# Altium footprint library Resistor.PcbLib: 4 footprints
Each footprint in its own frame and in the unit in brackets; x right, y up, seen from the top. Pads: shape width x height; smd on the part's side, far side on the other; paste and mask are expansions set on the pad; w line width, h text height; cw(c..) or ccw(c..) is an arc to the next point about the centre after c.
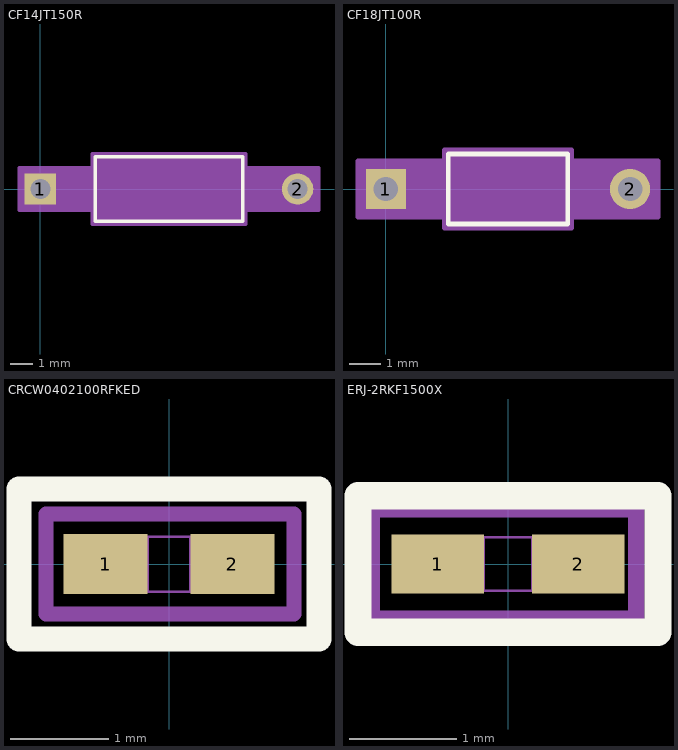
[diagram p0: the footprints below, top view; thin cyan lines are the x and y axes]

## CF14JT150R [mil] "150 Ohms ±5% 0.25W, 1/4W Through Hole Resistor Axial Carbon Film"
pads (2):
  rect 55x55 / inner round 60 / far side rect 55x55 hole 35 paste-99999 mask+0: 1(0,0)
  round 55 / inner round 60 / far side round 55 hole 35 paste-99999 mask+0: 2(450,0)
Top Overlay:
  lines w6: 96,-56.5 96,56.5 354,56.5 354,-56.5 96,-56.5
Mechanical 13:
  lines w1: 0,0 101,0 ; 349,0 450,0 ; 101,-51.5 101,51.5 349,51.5 349,-51.5 101,-51.5
  text "RefDes2" at 137.5,-25 h50
Mechanical 15:
  region: 91,-37.5 -37.5,-37.5 -37.5,37.5 91,37.5 91,61.5 359,61.5 359,37.5 487.5,37.5 487.5,-37.5 359,-37.5 359,-61.5 91,-61.5
  lines w6: -37.5,-37.5 91,-37.5 91,-61.5 359,-61.5 359,-37.5 487.5,-37.5 487.5,37.5 359,37.5 359,61.5 91,61.5 91,37.5 -37.5,37.5 -37.5,-37.5
3D body "STA_CF14_STP.step": height 103, standoff -110, extent -12.48,-52.25 462.48,50

## CF18JT100R [mil] "100 Ohms ±5% 0.125W, 1/8W Through Hole Resistor Axial Carbon Film"
pads (2):
  rect 51x51 hole 31 paste-99999 mask+0: 1(0,0)
  round 51 hole 31 paste-99999 mask+0: 2(310,0)
Top Overlay:
  lines w6: 79,-44.5 231,-44.5 231,44.5 79,44.5 79,-44.5
Mechanical 13:
  lines w1: 0,0 84,0 ; 226,0 310,0 ; 84,-39.5 226,-39.5 226,39.5 84,39.5 84,-39.5
Mechanical 15:
  region: 74,-35.5 -35.5,-35.5 -35.5,35.5 74,35.5 74,49.5 236,49.5 236,35.5 345.5,35.5 345.5,-35.5 236,-35.5 236,-49.5 74,-49.5
  lines w6: -35.5,-35.5 -35.5,35.5 74,35.5 74,49.5 236,49.5 236,35.5 345.5,35.5 345.5,-35.5 236,-35.5 236,-49.5 74,-49.5 74,-35.5 -35.5,-35.5
3D body "STA_CF18_STP.step": height 78.99, standoff -110, extent -10.51,-39.21 320.51,39.21

## CRCW0402100RFKED [mil] "100 Ohms ±1% 0.063W, 1/16W Chip Resistor 0402 (1005 Metric) Automotive AEC-Q200 Thick Film"
pads (2):
  rect 33.65x23.97 smd paste+0 mask+0: 1(-25.33,0) 2(25.33,0)
Top Overlay:
  lines w10: -60,-30 60,-30 60,30 -60,30 -60,-30
Mechanical 13:
  lines w1: -20.5,-11 -20.5,11 ; -20.5,-11 20.5,-11 ; -20.5,-11 -8.5,-11 -8.5,11 -20.5,11 ; -20.5,-11 -20.5,11 ; -20.5,11 20.5,11 ; 20.5,-11 20.5,11 ; 20.5,-11 20.5,11 ; 20.5,-11 8.5,-11 8.5,11 20.5,11
Mechanical 15:
  lines w6: -49.16,-20 -49.16,-5.99 -49.16,20 -19.09,20 19.09,20 50,20 50,10 50,-10 50,-20 -49.16,-20
3D body "RES_CRCW_0402.step": height 15.98, standoff 0, extent -20.51,-10.98 20.51,10.98

## ERJ-2RKF1500X [mil] "150 Ohms ±1% 0.1W, 1/10W Chip Resistor 0402 (1005 Metric) Automotive AEC-Q200 Thick Film"
pads (2):
  rect 33.81x21.68 smd paste+0 mask+0: 1(-25.76,0) 2(25.76,0)
Top Overlay:
  lines w10: -55,-25 55,-25 55,25 -55,25 -55,-25
Mechanical 13:
  lines w1: -20.67,-9.84 -20.67,9.84 ; -20.67,-9.84 20.67,-9.84 ; -20.67,-9.84 -8.86,-9.84 -8.86,9.84 -20.67,9.84 ; -20.67,-9.84 -20.67,9.84 ; -20.67,9.84 20.67,9.84 ; 20.67,-9.84 20.67,9.84 ; 20.67,-9.84 20.67,9.84 ; 20.67,-9.84 8.86,-9.84 8.86,9.84 20.67,9.84
Mechanical 15:
  lines w6: -48.49,-20 -46.87,-20 -31.33,-20 31.33,-20 45,-20 ; -39.1,-20 -50,-20 -50,-15.42 -50,20 -31.33,20 31.33,20 47,20 47,-20
3D body "RC0402N_PAN.step": height 27.99, standoff 0, extent -20.67,-9.84 20.67,9.84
